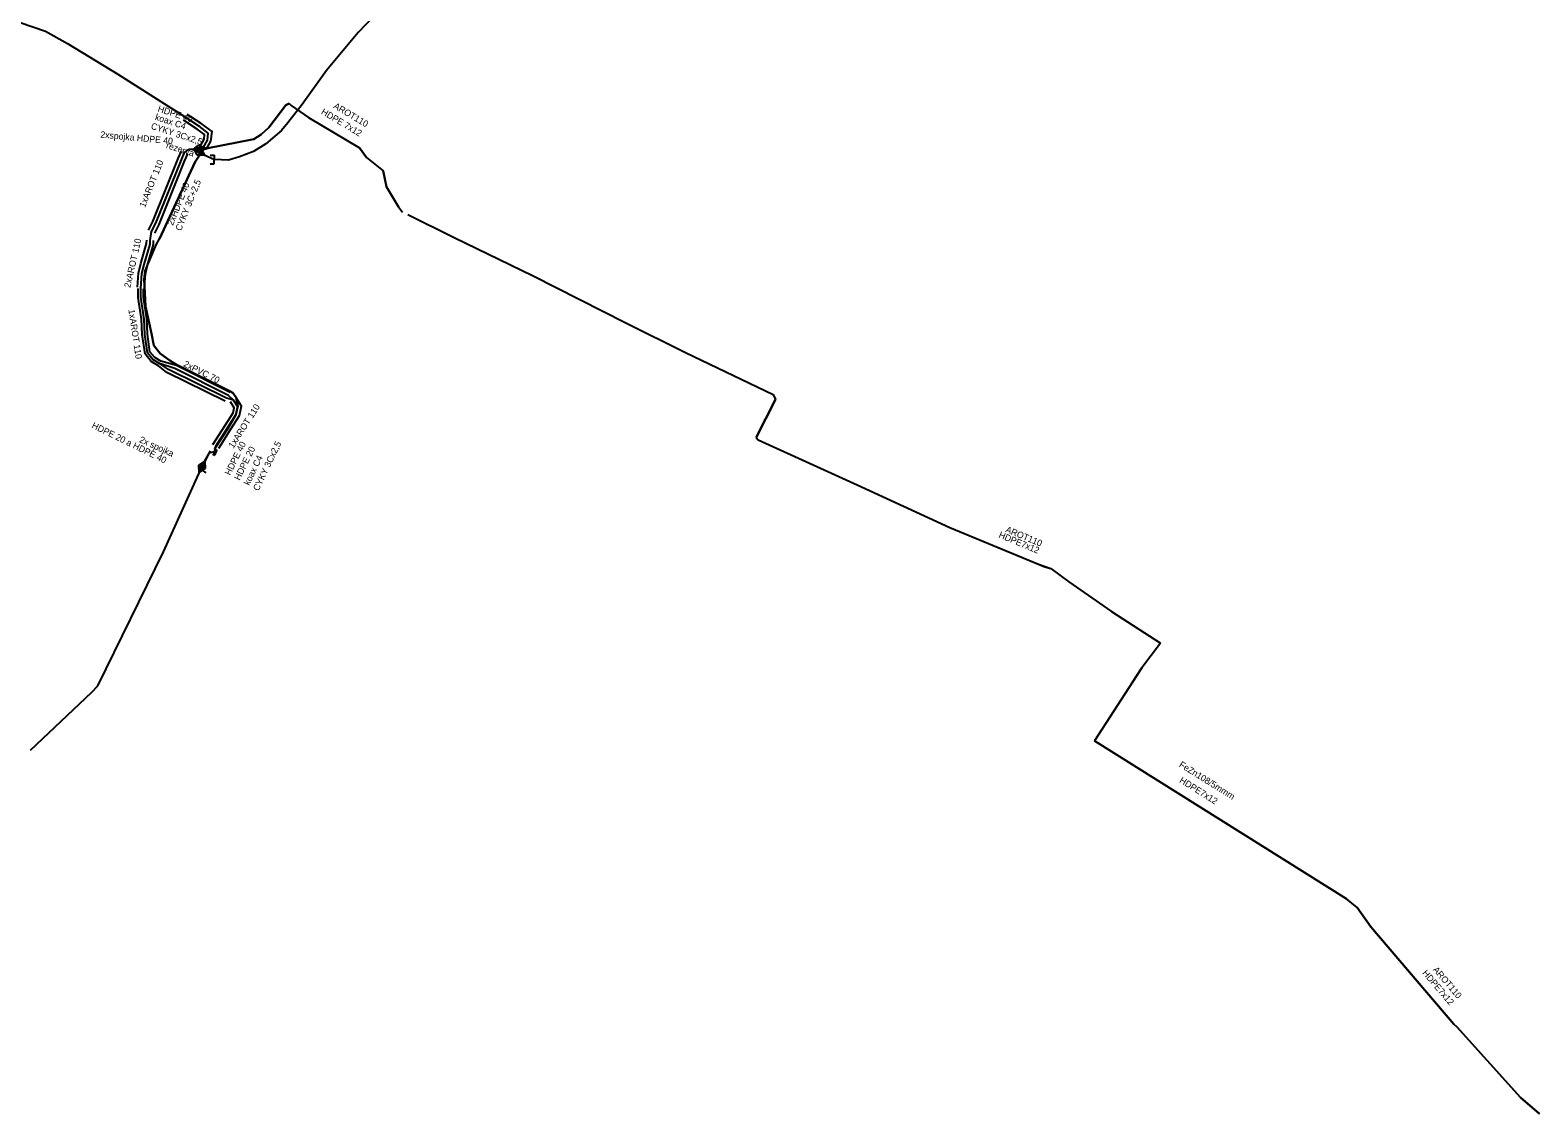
# Model space of a CAD drawing. Extents: x -651943 to -618711, y -1138561 to -1100552.
# Drawn here: x -641970 to -641795.5, y -1113895.7 to -1113770.2 of the extents above; entities that cross this region are included whole.
import ezdxf

# ---------------------------------------------------------------- set-up
doc = ezdxf.new("R2010")
doc.units = 0
for name, color, linetype in [('KT optika', 7, 'Continuous'), ('KT trasa', 7, 'Continuous'), ('KT zařízení', 7, 'Continuous')]:
    doc.layers.add(name, color=color, linetype=linetype)

# ---------------------------------------------------------------- blocks, each defined once
blk = doc.blocks.new('TVSPO_1')
at = {"layer": 'KT zařízení'}
for p, q in [((-0.074, 0.002), (0, 0.044)), ((-0.001, -0.041), (-0.074, 0.002)), ((-0.035, 0), (0, 0.02)), ((0.073, 0.001), (-0.001, -0.041)), ((0, 0.044), (0.073, 0.001)), ((0, 0.02), (0.035, 0)), ((0.035, 0), (0, -0.02)), ((0, -0.02), (-0.035, 0))]:
    blk.add_line(p, q, dxfattribs=at)
blk = doc.blocks.new('TVREZ')
at = {"layer": 'KT zařízení'}
for p, q in [((-0.05, 0.05), (0, 0.05)), ((0, -0.05), (0, 0.05)), ((-0.05, -0.05), (0, -0.05))]:
    blk.add_line(p, q, dxfattribs=at)
blk = doc.blocks.new('POINT_DISPLAY')
blk.add_line((0, 0), (0, 0))

msp = doc.modelspace()

# ---------------------------------------------------------------- linework, layer by layer
at = {"layer": 'KT optika'}
for p, q in [((-641971.18, -1113769.37), (-641968.27, -1113770.37)), ((-641971.18, -1113769.37), (-641968.27, -1113770.37)), ((-641968.27, -1113770.37), (-641965.71, -1113771.79)), ((-641968.27, -1113770.37), (-641965.71, -1113771.79)), ((-641965.71, -1113771.79), (-641959.88, -1113775.34)), ((-641965.71, -1113771.79), (-641959.88, -1113775.34)), ((-641959.88, -1113775.34), (-641952.08, -1113780.33)), ((-641959.88, -1113775.34), (-641952.08, -1113780.33)), ((-641940.45, -1113778.94), (-641942.41, -1113781.51)), ((-641940.08, -1113778.72), (-641940.45, -1113778.94)), ((-641939.84, -1113778.96), (-641940.08, -1113778.72)), ((-641939.84, -1113778.96), (-641937.81, -1113780.34)), ((-641952.08, -1113780.33), (-641950.47, -1113781.36)), ((-641952.08, -1113780.33), (-641950.47, -1113781.36)), ((-641949.42, -1113782.15), (-641950.47, -1113781.36)), ((-641942.41, -1113781.51), (-641943.3, -1113782.32)), ((-641937.81, -1113780.34), (-641931.94, -1113783.86)), ((-641950.01, -1113783.88), (-641949.53, -1113782.96)), ((-641949.53, -1113782.96), (-641949.42, -1113782.15)), ((-641944.15, -1113782.84), (-641949.49, -1113783.9)), ((-641943.3, -1113782.32), (-641944.15, -1113782.84)), ((-641952.54, -1113785.25), (-641952.16, -1113784.41)), ((-641952.54, -1113785.25), (-641952.16, -1113784.41)), ((-641952.16, -1113784.41), (-641951.65, -1113784)), ((-641952.16, -1113784.41), (-641951.65, -1113784)), ((-641951.65, -1113784), (-641951.04, -1113784.02)), ((-641951.65, -1113784), (-641951.04, -1113784.02)), ((-641951.04, -1113784.02), (-641950.5, -1113783.97)), ((-641951.04, -1113784.02), (-641950.5, -1113783.97)), ((-641949.98, -1113784.05), (-641950.95, -1113785.5)), ((-641950.94, -1113784.02), (-641950.47, -1113784.32)), ((-641950.94, -1113784.02), (-641950.47, -1113784.32)), ((-641950.5, -1113783.97), (-641950.01, -1113783.88)), ((-641950.47, -1113784.32), (-641949.92, -1113784.68)), ((-641949.49, -1113783.9), (-641949.98, -1113784.05)), ((-641949.92, -1113784.68), (-641948.71, -1113785.22)), ((-641949.92, -1113784.68), (-641948.71, -1113785.22)), ((-641949.92, -1113784.68), (-641948.71, -1113785.22)), ((-641931.1, -1113784.97), (-641931.94, -1113783.86)), ((-641931.1, -1113784.97), (-641929.2, -1113786.52)), ((-641955.48, -1113792.57), (-641952.54, -1113785.25)), ((-641955.48, -1113792.57), (-641952.54, -1113785.25)), ((-641955.09, -1113794.41), (-641950.95, -1113785.5)), ((-641928.81, -1113788.38), (-641929.2, -1113786.52)), ((-641927.41, -1113790.7), (-641928.81, -1113788.38)), ((-641927.41, -1113790.7), (-641926.95, -1113791.3)), ((-641926.32, -1113791.59), (-641920.97, -1113794.23)), ((-641956.15, -1113794.57), (-641955.99, -1113793.56)), ((-641955.99, -1113793.56), (-641955.48, -1113792.57)), ((-641956.86, -1113797.35), (-641956.16, -1113795)), ((-641956.72, -1113798.08), (-641955.42, -1113795)), ((-641956.16, -1113795), (-641956.15, -1113794.57)), ((-641955.42, -1113795), (-641955.09, -1113794.41)), ((-641920.97, -1113794.23), (-641911.83, -1113798.69)), ((-641957.1, -1113798.41), (-641956.86, -1113797.35)), ((-641957.23, -1113800.16), (-641957.1, -1113798.41)), ((-641956.73, -1113798.34), (-641956.84, -1113799.09)), ((-641956.84, -1113799.09), (-641956.68, -1113802.19)), ((-641911.83, -1113798.69), (-641901.09, -1113804.12)), ((-641957.23, -1113801.15), (-641957.23, -1113800.16)), ((-641956.85, -1113803.68), (-641957.23, -1113801.15)), ((-641956.68, -1113802.19), (-641955.98, -1113805.34)), ((-641956.77, -1113805.45), (-641956.85, -1113803.68)), ((-641901.09, -1113804.12), (-641894.19, -1113807.57)), ((-641956.46, -1113807.58), (-641956.77, -1113805.45)), ((-641955.98, -1113805.34), (-641955.72, -1113806.74)), ((-641955.83, -1113808.36), (-641956.46, -1113807.58)), ((-641955.72, -1113806.74), (-641954.99, -1113807.66)), ((-641954.99, -1113807.66), (-641953.89, -1113808.47)), ((-641894.19, -1113807.57), (-641884.03, -1113812.4)), ((-641955.07, -1113808.82), (-641955.83, -1113808.36)), ((-641954.03, -1113809.52), (-641955.07, -1113808.82)), ((-641953.28, -1113809.4), (-641955.07, -1113808.82)), ((-641947.3, -1113812.83), (-641954.03, -1113809.52)), ((-641953.89, -1113808.47), (-641953.06, -1113808.99)), ((-641947.07, -1113812.54), (-641953.28, -1113809.4)), ((-641946.93, -1113812.04), (-641953.06, -1113808.99)), ((-641946.51, -1113813.06), (-641947.3, -1113812.83)), ((-641946.51, -1113813.06), (-641947.07, -1113812.54)), ((-641946.93, -1113812.04), (-641946.59, -1113812.23)), ((-641946.59, -1113812.23), (-641946.2, -1113812.76)), ((-641946.02, -1113813.86), (-641946.51, -1113813.06)), ((-641946.2, -1113812.76), (-641945.99, -1113813.78)), ((-641883.77, -1113813.01), (-641886.02, -1113817.38)), ((-641884.03, -1113812.4), (-641883.77, -1113813.01)), ((-641946.22, -1113814.76), (-641947.22, -1113816.43)), ((-641947.11, -1113816.14), (-641946.18, -1113814.7)), ((-641945.99, -1113813.78), (-641946.22, -1113814.76)), ((-641946.18, -1113814.7), (-641946.02, -1113813.86)), ((-641947.22, -1113816.43), (-641948.66, -1113818.65)), ((-641948.56, -1113818.41), (-641947.11, -1113816.14)), ((-641886.02, -1113817.38), (-641885.79, -1113817.65)), ((-641885.79, -1113817.65), (-641874.33, -1113822.86)), ((-641949.35, -1113819.2), (-641950.14, -1113820.8)), ((-641949.9, -1113820.24), (-641949.15, -1113818.94)), ((-641949.89, -1113820.24), (-641949.15, -1113818.94)), ((-641948.74, -1113819.06), (-641949.35, -1113819.2)), ((-641948.71, -1113819.14), (-641948.56, -1113818.41)), ((-641948.66, -1113818.65), (-641948.56, -1113819.04)), ((-641954.61, -1113830.62), (-641950.5, -1113821.61)), ((-641954.61, -1113830.62), (-641950.5, -1113821.61)), ((-641950.5, -1113821.61), (-641949.9, -1113820.24)), ((-641950.5, -1113821.61), (-641949.89, -1113820.24)), ((-641950.14, -1113820.8), (-641950.12, -1113821.16)), ((-641950.12, -1113821.16), (-641949.71, -1113821.47)), ((-641874.33, -1113822.86), (-641863.58, -1113827.79)), ((-641863.58, -1113827.79), (-641852.62, -1113832.37)), ((-641962.22, -1113846.15), (-641954.61, -1113830.62)), ((-641962.21, -1113846.15), (-641954.61, -1113830.62)), ((-641853.35, -1113832.04), (-641851.9, -1113832.54)), ((-641851.9, -1113832.54), (-641849.82, -1113834.08)), ((-641849.82, -1113834.08), (-641844.9, -1113837.55)), ((-641844.9, -1113837.55), (-641839.23, -1113841.2)), ((-641839.23, -1113841.2), (-641841.38, -1113844.04)), ((-641842.44, -1113845.71), (-641841.38, -1113844.04)), ((-641962.91, -1113846.85), (-641962.22, -1113846.15)), ((-641962.9, -1113846.85), (-641962.21, -1113846.15)), ((-641842.44, -1113845.71), (-641846.85, -1113852.49)), ((-641970.01, -1113853.57), (-641962.92, -1113846.86)), ((-641970.01, -1113853.57), (-641962.92, -1113846.86)), ((-641846.85, -1113852.49), (-641817.69, -1113870.79)), ((-641816.45, -1113871.81), (-641817.69, -1113870.79)), ((-641816.45, -1113871.81), (-641814.88, -1113874.04)), ((-641814.88, -1113874.04), (-641805.26, -1113885.29)), ((-641805.26, -1113885.29), (-641804.92, -1113885.61)), ((-641804.92, -1113885.61), (-641797.54, -1113893.77)), ((-641797.54, -1113893.77), (-641795.34, -1113895.68))]:
    msp.add_line(p, q, dxfattribs=at)
msp.add_lwpolyline([(-641930.29, -1113768.64), (-641932.08, -1113770.5), (-641935.74, -1113774.92), (-641938.57, -1113778.85), (-641940.2, -1113780.96), (-641940.96, -1113781.84), (-641942.78, -1113783.4), (-641944.19, -1113784.27), (-641945.81, -1113784.92), (-641947.08, -1113785.29), (-641948.71, -1113785.22)], dxfattribs=at)
at = {"layer": 'KT trasa'}
for p, q in [((-641971.18, -1113769.37), (-641968.27, -1113770.37)), ((-641968.27, -1113770.37), (-641965.71, -1113771.79)), ((-641965.71, -1113771.79), (-641959.88, -1113775.34)), ((-641959.88, -1113775.34), (-641952.08, -1113780.33)), ((-641940.45, -1113778.94), (-641942.41, -1113781.51)), ((-641940.08, -1113778.72), (-641940.45, -1113778.94)), ((-641939.84, -1113778.96), (-641940.08, -1113778.72)), ((-641939.84, -1113778.96), (-641937.81, -1113780.34)), ((-641952.08, -1113780.33), (-641950.47, -1113781.36)), ((-641949.42, -1113782.15), (-641950.47, -1113781.36)), ((-641942.41, -1113781.51), (-641943.3, -1113782.32)), ((-641937.81, -1113780.34), (-641931.94, -1113783.86)), ((-641950.01, -1113783.88), (-641949.53, -1113782.96)), ((-641949.53, -1113782.96), (-641949.42, -1113782.15)), ((-641944.15, -1113782.84), (-641949.49, -1113783.9)), ((-641943.3, -1113782.32), (-641944.15, -1113782.84)), ((-641952.54, -1113785.25), (-641952.16, -1113784.41)), ((-641952.16, -1113784.41), (-641951.65, -1113784)), ((-641951.65, -1113784), (-641951.04, -1113784.02)), ((-641951.04, -1113784.02), (-641950.5, -1113783.97)), ((-641949.98, -1113784.05), (-641950.95, -1113785.5)), ((-641950.94, -1113784.02), (-641950.47, -1113784.32)), ((-641950.5, -1113783.97), (-641950.01, -1113783.88)), ((-641950.47, -1113784.32), (-641949.92, -1113784.68)), ((-641949.49, -1113783.9), (-641949.98, -1113784.05)), ((-641949.92, -1113784.68), (-641948.71, -1113785.22)), ((-641931.1, -1113784.97), (-641931.94, -1113783.86)), ((-641931.1, -1113784.97), (-641929.2, -1113786.52)), ((-641955.48, -1113792.57), (-641952.54, -1113785.25)), ((-641955.09, -1113794.41), (-641950.95, -1113785.5)), ((-641928.81, -1113788.38), (-641929.2, -1113786.52)), ((-641927.41, -1113790.7), (-641928.81, -1113788.38)), ((-641927.41, -1113790.7), (-641926.95, -1113791.3)), ((-641926.32, -1113791.59), (-641920.97, -1113794.23)), ((-641956.15, -1113794.57), (-641955.99, -1113793.56)), ((-641955.99, -1113793.56), (-641955.48, -1113792.57)), ((-641956.86, -1113797.35), (-641956.16, -1113795)), ((-641956.72, -1113798.08), (-641955.42, -1113795)), ((-641956.16, -1113795), (-641956.15, -1113794.57)), ((-641955.42, -1113795), (-641955.09, -1113794.41)), ((-641920.97, -1113794.23), (-641911.83, -1113798.69)), ((-641957.1, -1113798.41), (-641956.86, -1113797.35)), ((-641957.23, -1113800.16), (-641957.1, -1113798.41)), ((-641956.73, -1113798.34), (-641956.84, -1113799.09)), ((-641956.84, -1113799.09), (-641956.68, -1113802.19)), ((-641911.83, -1113798.69), (-641901.09, -1113804.12)), ((-641957.23, -1113801.15), (-641957.23, -1113800.16)), ((-641956.85, -1113803.68), (-641957.23, -1113801.15)), ((-641956.68, -1113802.19), (-641955.98, -1113805.34)), ((-641956.77, -1113805.45), (-641956.85, -1113803.68)), ((-641901.09, -1113804.12), (-641894.19, -1113807.57)), ((-641956.46, -1113807.58), (-641956.77, -1113805.45)), ((-641955.98, -1113805.34), (-641955.72, -1113806.74)), ((-641955.83, -1113808.36), (-641956.46, -1113807.58)), ((-641955.72, -1113806.74), (-641954.99, -1113807.66)), ((-641954.99, -1113807.66), (-641953.89, -1113808.47)), ((-641894.19, -1113807.57), (-641884.03, -1113812.4)), ((-641955.07, -1113808.82), (-641955.83, -1113808.36)), ((-641954.03, -1113809.52), (-641955.07, -1113808.82)), ((-641953.28, -1113809.4), (-641955.07, -1113808.82)), ((-641947.3, -1113812.83), (-641954.03, -1113809.52)), ((-641953.89, -1113808.47), (-641953.06, -1113808.99)), ((-641947.07, -1113812.54), (-641953.28, -1113809.4)), ((-641946.93, -1113812.04), (-641953.06, -1113808.99)), ((-641946.51, -1113813.06), (-641947.3, -1113812.83)), ((-641946.51, -1113813.06), (-641947.07, -1113812.54)), ((-641946.93, -1113812.04), (-641946.59, -1113812.23)), ((-641946.59, -1113812.23), (-641946.2, -1113812.76)), ((-641946.02, -1113813.86), (-641946.51, -1113813.06)), ((-641946.2, -1113812.76), (-641945.99, -1113813.78)), ((-641883.77, -1113813.01), (-641886.02, -1113817.38)), ((-641884.03, -1113812.4), (-641883.77, -1113813.01)), ((-641946.22, -1113814.76), (-641947.22, -1113816.43)), ((-641947.11, -1113816.14), (-641946.18, -1113814.7)), ((-641945.99, -1113813.78), (-641946.22, -1113814.76)), ((-641946.18, -1113814.7), (-641946.02, -1113813.86)), ((-641947.22, -1113816.43), (-641948.66, -1113818.65)), ((-641948.56, -1113818.41), (-641947.11, -1113816.14)), ((-641886.02, -1113817.38), (-641885.79, -1113817.65)), ((-641885.79, -1113817.65), (-641874.33, -1113822.86)), ((-641949.35, -1113819.2), (-641950.14, -1113820.8)), ((-641949.9, -1113820.24), (-641949.15, -1113818.94)), ((-641949.89, -1113820.24), (-641949.15, -1113818.94)), ((-641948.74, -1113819.06), (-641949.35, -1113819.2)), ((-641948.71, -1113819.14), (-641948.56, -1113818.41)), ((-641948.66, -1113818.65), (-641948.56, -1113819.04)), ((-641954.61, -1113830.62), (-641950.5, -1113821.61)), ((-641954.61, -1113830.62), (-641950.5, -1113821.61)), ((-641950.5, -1113821.61), (-641949.9, -1113820.24)), ((-641950.5, -1113821.61), (-641949.89, -1113820.24)), ((-641950.14, -1113820.8), (-641950.12, -1113821.16)), ((-641950.12, -1113821.16), (-641949.71, -1113821.47)), ((-641874.33, -1113822.86), (-641863.58, -1113827.79)), ((-641863.58, -1113827.79), (-641852.62, -1113832.37)), ((-641962.22, -1113846.15), (-641954.61, -1113830.62)), ((-641962.21, -1113846.15), (-641954.61, -1113830.62)), ((-641853.35, -1113832.04), (-641851.9, -1113832.54)), ((-641851.9, -1113832.54), (-641849.82, -1113834.08)), ((-641849.82, -1113834.08), (-641844.9, -1113837.55)), ((-641844.9, -1113837.55), (-641839.23, -1113841.2)), ((-641839.23, -1113841.2), (-641841.38, -1113844.04)), ((-641842.44, -1113845.71), (-641841.38, -1113844.04)), ((-641962.91, -1113846.85), (-641962.22, -1113846.15)), ((-641962.9, -1113846.85), (-641962.21, -1113846.15)), ((-641842.44, -1113845.71), (-641846.85, -1113852.49)), ((-641970.01, -1113853.57), (-641962.92, -1113846.86)), ((-641970.01, -1113853.57), (-641962.92, -1113846.86)), ((-641846.85, -1113852.49), (-641817.69, -1113870.79)), ((-641816.45, -1113871.81), (-641817.69, -1113870.79)), ((-641816.45, -1113871.81), (-641814.88, -1113874.04)), ((-641814.88, -1113874.04), (-641805.26, -1113885.29)), ((-641805.26, -1113885.29), (-641804.92, -1113885.61)), ((-641804.92, -1113885.61), (-641797.54, -1113893.77)), ((-641797.54, -1113893.77), (-641795.34, -1113895.68))]:
    msp.add_line(p, q, dxfattribs=at)
msp.add_lwpolyline([(-641930.29, -1113768.64), (-641932.08, -1113770.5), (-641935.74, -1113774.92), (-641938.57, -1113778.85), (-641940.2, -1113780.96), (-641940.96, -1113781.84), (-641942.78, -1113783.4), (-641944.19, -1113784.27), (-641945.81, -1113784.92), (-641947.08, -1113785.29), (-641948.71, -1113785.22)], dxfattribs=at)
at = {"layer": 'KT zařízení'}
for p, q in [((-641942.41, -1113781.51), (-641940.45, -1113778.94)), ((-641940.45, -1113778.94), (-641940.08, -1113778.72)), ((-641940.08, -1113778.72), (-641939.84, -1113778.96)), ((-641939.84, -1113778.96), (-641937.81, -1113780.34)), ((-641943.3, -1113782.32), (-641942.41, -1113781.51)), ((-641937.81, -1113780.34), (-641931.94, -1113783.86)), ((-641949.49, -1113783.9), (-641944.15, -1113782.84)), ((-641944.15, -1113782.84), (-641943.3, -1113782.32)), ((-641950.95, -1113785.5), (-641949.98, -1113784.05)), ((-641949.98, -1113784.05), (-641949.49, -1113783.9)), ((-641931.94, -1113783.86), (-641931.1, -1113784.97)), ((-641931.1, -1113784.97), (-641929.2, -1113786.52)), ((-641950.95, -1113785.5), (-641955.09, -1113794.41)), ((-641929.2, -1113786.52), (-641928.81, -1113788.38)), ((-641928.81, -1113788.38), (-641927.41, -1113790.7)), ((-641927.41, -1113790.7), (-641926.95, -1113791.3)), ((-641926.32, -1113791.59), (-641920.97, -1113794.23)), ((-641956.72, -1113798.08), (-641955.42, -1113795)), ((-641955.42, -1113795), (-641955.09, -1113794.41)), ((-641920.97, -1113794.23), (-641911.83, -1113798.69)), ((-641956.84, -1113799.09), (-641956.72, -1113798.08)), ((-641956.68, -1113802.19), (-641956.84, -1113799.09)), ((-641911.83, -1113798.69), (-641901.09, -1113804.12)), ((-641955.98, -1113805.34), (-641956.68, -1113802.19)), ((-641901.09, -1113804.12), (-641894.19, -1113807.57)), ((-641955.72, -1113806.74), (-641955.98, -1113805.34)), ((-641954.99, -1113807.66), (-641955.72, -1113806.74)), ((-641953.89, -1113808.47), (-641954.99, -1113807.66)), ((-641894.19, -1113807.57), (-641884.03, -1113812.4)), ((-641953.06, -1113808.99), (-641953.89, -1113808.47)), ((-641946.89, -1113812.18), (-641953.1, -1113809.04)), ((-641946.93, -1113812.04), (-641953.06, -1113808.99)), ((-641947.48, -1113813.19), (-641954.21, -1113809.88)), ((-641946.59, -1113812.23), (-641946.93, -1113812.04)), ((-641946.2, -1113812.76), (-641946.59, -1113812.23)), ((-641945.99, -1113813.78), (-641946.2, -1113812.76)), ((-641886.02, -1113817.38), (-641883.77, -1113813.01)), ((-641884.03, -1113812.4), (-641883.77, -1113813.01)), ((-641947.22, -1113816.43), (-641946.22, -1113814.76)), ((-641946.22, -1113814.76), (-641945.99, -1113813.78)), ((-641948.66, -1113818.65), (-641947.22, -1113816.43)), ((-641886.02, -1113817.38), (-641885.79, -1113817.65)), ((-641885.79, -1113817.65), (-641874.33, -1113822.86)), ((-641948.56, -1113819.04), (-641948.66, -1113818.65)), ((-641874.33, -1113822.86), (-641863.58, -1113827.79)), ((-641863.58, -1113827.79), (-641853.35, -1113832.04)), ((-641853.35, -1113832.04), (-641852.62, -1113832.37)), ((-641852.62, -1113832.37), (-641851.9, -1113832.54)), ((-641851.9, -1113832.54), (-641849.82, -1113834.08)), ((-641849.82, -1113834.08), (-641844.9, -1113837.55)), ((-641844.9, -1113837.55), (-641839.23, -1113841.2)), ((-641839.23, -1113841.2), (-641841.38, -1113844.04)), ((-641841.38, -1113844.04), (-641842.44, -1113845.71)), ((-641842.44, -1113845.71), (-641846.85, -1113852.49)), ((-641817.69, -1113870.79), (-641846.85, -1113852.49)), ((-641816.45, -1113871.81), (-641817.69, -1113870.79)), ((-641814.88, -1113874.04), (-641816.45, -1113871.81)), ((-641805.26, -1113885.29), (-641814.88, -1113874.04)), ((-641804.92, -1113885.61), (-641805.26, -1113885.29)), ((-641797.54, -1113893.77), (-641804.92, -1113885.61)), ((-641795.34, -1113895.68), (-641797.54, -1113893.77))]:
    msp.add_line(p, q, dxfattribs=at)
for points in [[(-641950.36, -1113783.7), (-641949.92, -1113782.84), (-641949.85, -1113782.33), (-641950.7, -1113781.69), (-641952.3, -1113780.67)], [(-641949.66, -1113784.06), (-641949.14, -1113783.08), (-641948.99, -1113781.97), (-641950.24, -1113781.03), (-641951.86, -1113779.99)], [(-641956.35, -1113793.38), (-641955.84, -1113792.4), (-641952.91, -1113785.09), (-641952.52, -1113784.25)], [(-641955.63, -1113793.74), (-641955.12, -1113792.74), (-641952.17, -1113785.41), (-641951.8, -1113784.57)], [(-641957.62, -1113799.97), (-641957.5, -1113798.35), (-641957.25, -1113797.25), (-641956.56, -1113794.94), (-641956.55, -1113794.56)], [(-641956.81, -1113799.88), (-641956.7, -1113798.47), (-641956.47, -1113797.45), (-641955.76, -1113795.06), (-641955.75, -1113794.58)], [(-641954.21, -1113809.88), (-641955.2, -1113809.09), (-641956.03, -1113808.59), (-641956.74, -1113807.7), (-641957.07, -1113805.48), (-641957.15, -1113803.71), (-641957.53, -1113801.17), (-641957.53, -1113800.15)], [(-641953.1, -1113809.04), (-641954.93, -1113808.55), (-641955.63, -1113808.13), (-641956.18, -1113807.46), (-641956.47, -1113805.42), (-641956.55, -1113803.65), (-641956.93, -1113801.13), (-641956.93, -1113800.18)], [(-641948.22, -1113818.62), (-641946.77, -1113816.36), (-641945.8, -1113814.85), (-641945.6, -1113813.78), (-641946.17, -1113812.85)], [(-641948.9, -1113818.2), (-641947.45, -1113815.92), (-641946.56, -1113814.55), (-641946.44, -1113813.94), (-641946.85, -1113813.27)]]:
    msp.add_lwpolyline(points, dxfattribs=at)
msp.add_lwpolyline([(-641948.68, -1113819.43), (-641948.42, -1113818.89), (-641948.6, -1113818.81), (-641948.86, -1113819.35)], close=True, dxfattribs=at)

# ---------------------------------------------------------------- block references
at = {"layer": 'KT optika'}
msp.add_blockref('POINT_DISPLAY', (-641950.94, -1113784.02), dxfattribs=at)
msp.add_blockref('POINT_DISPLAY', (-641950.94, -1113784.02), dxfattribs=at)
at = {"layer": 'KT trasa'}
msp.add_blockref('POINT_DISPLAY', (-641950.94, -1113784.02), dxfattribs=at)
at = {"layer": 'KT zařízení'}
for name, p, xscale, yscale, rotation in [('TVSPO_1', (-641950.5, -1113783.97), 9.99999371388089, 9.999993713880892, -170.7859839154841), ('TVSPO_1', (-641950.47, -1113784.32), 9.999999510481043, 9.999999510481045, 149.0041680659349), ('TVREZ', (-641948.71, -1113785.22), 10.000008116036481, 10.000008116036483, -1.7761352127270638), ('TVSPO_1', (-641950.14, -1113820.8), 9.999984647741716, 9.999984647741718, 63.96294234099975)]:
    msp.add_blockref(name, p, dxfattribs=dict(at, xscale=xscale, yscale=yscale, rotation=rotation))

# ---------------------------------------------------------------- texts
for s, rotation, p in [('koax C4', 341.9602, (-641955.65, -1113780.61)), ('HDPE 40', 341.9602, (-641955.34, -1113779.64)), ('HDPE 7x12', 329.0506, (-641936.43, -1113779.89)), ('AROT110', 329.0506, (-641935.01, -1113779.22)), ('CYKY 3Cx2,5', 341.9602, (-641956.13, -1113781.64)), ('2xspojka HDPE 40', 354.7406, (-641961.94, -1113782.68)), ('rezerva', 341.9602, (-641954.37, -1113783.86)), ('1xAROT 110', 68.1203, (-641956.75, -1113790.83)), ('2xHDPE 40', 68.1151, (-641953.52, -1113792.92)), ('CYKY 3C+2,5', 68.1177, (-641952.58, -1113793.54)), ('2xAROT 110', 77.2182, (-641958.45, -1113800.11)), ('1xAROT 110', 278.5497, (-641958.68, -1113802.61)), ('2xPVC 70', 333.1772, (-641952.37, -1113809.12)), ('1xAROT 110', 57.4424, (-641946.52, -1113818.71)), ('HDPE 20 a HDPE 40', 333.8107, (-641962.99, -1113816.24)), ('2x spojka', 335.49, (-641957.48, -1113817.9)), ('HDPE 40', 63.7221, (-641946.89, -1113821.84)), ('CYKY 3Cx2,5', 64.5405, (-641943.61, -1113823.64)), ('HDPE 20', 63.7221, (-641945.81, -1113822.41)), ('koax C4', 64.5405, (-641944.68, -1113823)), ('HDPE7x12', 337.3208, (-641858.01, -1113828.94)), ('AROT110', 337.3208, (-641857.22, -1113828.32)), ('FeZn108/5mmm', 327.8888, (-641837.14, -1113855.45)), ('HDPE7x12', 327.8888, (-641837.1, -1113857.26)), ('HDPE7x12', 310.5341, (-641808.97, -1113879.41)), ('AROT110', 310.5341, (-641807.74, -1113879.03))]:
    msp.add_text(s, height=0.75, rotation=rotation, dxfattribs=at).set_placement(p)

doc.saveas('drawing.dxf')
